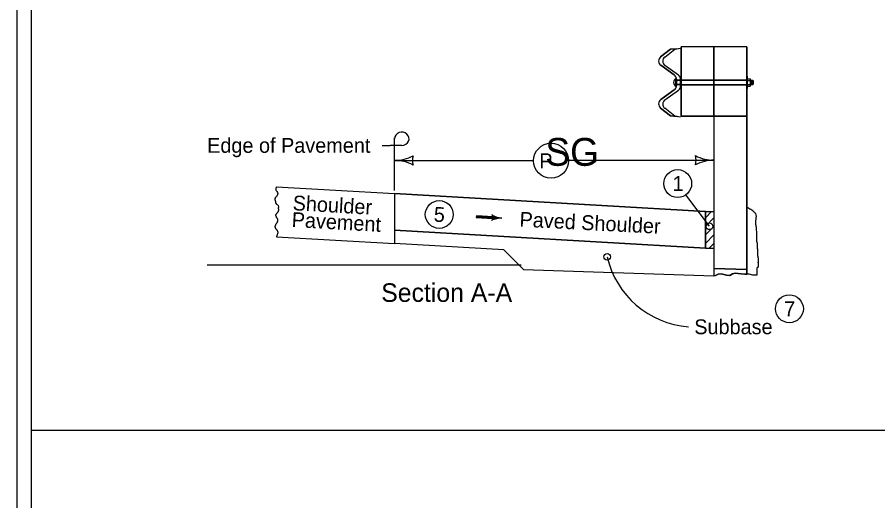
# Model space of a CAD drawing. Extents: x 9538 to 81668, y 7600 to 11751.
# Drawn here: x 24533 to 25461, y 8764 to 9286 of the extents above; entities that cross this region are included whole.
import ezdxf

# ---------------------------------------------------------------- set-up
doc = ezdxf.new("R2010")
doc.units = 0
for name, color, linetype in [('Default', 7, 'Continuous'), ('DsnShtMinorGrid13', 7, 'Continuous'), ('DsnShtMinorGrid14', 7, 'Continuous'), ('dsnStdCells', 7, 'Continuous'), ('dsnStdDimension', 7, 'Continuous'), ('dsnStdNameDate', 7, 'Continuous'), ('dsnStdNote', 7, 'Continuous'), ('dsnStdShading', 7, 'Continuous'), ('dsnStdTable', 7, 'Continuous')]:
    doc.layers.add(name, color=color, linetype=linetype)

msp = doc.modelspace()

# ---------------------------------------------------------------- linework, layer by layer
at = {"layer": 'Default'}
msp.add_lwpolyline([(24532.55, 9944.02), (27667.56, 9944.02), (27667.56, 7924.02), (24532.55, 7924.02)], close=True, dxfattribs=at)
at = {"layer": 'DsnShtMinorGrid13'}
for centre, radius in [((25244.81, 9106.23), 15), ((24987.61, 9072.86), 15), ((25278.94, 9060.11), 3.58), ((25365.26, 8971.18), 15)]:
    msp.add_circle(centre, radius, dxfattribs=at)
at = {"layer": 'DsnShtMinorGrid14'}
msp.add_circle((25168.62, 9027.15), 3.54, dxfattribs=at)
at = {"layer": 'dsnStdCells'}
for p, q in [((25226.58, 9233.67), (25241.09, 9223.26)), ((25241.09, 9207.18), (25226.58, 9196.77))]:
    msp.add_line(p, q, dxfattribs=at)
for points in [[(25283.87, 9217.88), (25283.87, 9253.55), (25248.33, 9253.55), (25248.33, 9217.88), (25248.33, 9217.88), (25283.87, 9217.88)], [(25319.42, 9217.88), (25319.42, 9221.88), (25319.42, 9253.55), (25283.87, 9253.55), (25283.87, 9217.88), (25319.42, 9217.88)], [(25230.83, 9242.57), (25230.82, 9242.56), (25241.6, 9250.97), (25243.48, 9251.3), (25237.15, 9251.19), (25226.39, 9242.79)], [(25245.54, 9223.04), (25245.57, 9223.02), (25231, 9233.48), (25231.03, 9233.45)], [(25243.49, 9218.63), (25243.49, 9217.55), (25247.93, 9217.55), (25247.93, 9218.41), (25247.93, 9218.41)], [(25248.33, 9217.55), (25248.33, 9212.88), (25248.33, 9212.88), (25283.87, 9212.88), (25283.87, 9217.55), (25248.33, 9217.55), (25248.33, 9217.55)], [(25319.42, 9212.88), (25319.42, 9217.55), (25283.87, 9217.55), (25283.87, 9212.88), (25319.42, 9212.88)], [(25231.03, 9196.55), (25231, 9196.53), (25245.57, 9206.99), (25245.54, 9206.96)], [(25247.93, 9211.6), (25247.93, 9211.6), (25247.93, 9212.88), (25243.49, 9212.88), (25243.49, 9211.82), (25243.49, 9212.88), (25243.49, 9212.88), (25243.49, 9211.82)], [(25248.33, 9212.55), (25248.33, 9178.9), (25283.87, 9178.9), (25283.87, 9212.55), (25248.33, 9212.55)], [(25319.42, 9178.9), (25319.42, 9208.55), (25319.42, 9212.55), (25283.87, 9212.55), (25283.87, 9178.9), (25319.42, 9178.9)], [(25226.39, 9187.65), (25237.15, 9179.25), (25244.26, 9178.56), (25241.6, 9179.03), (25230.82, 9187.44), (25230.83, 9187.43)], [(25319.42, 9013.57), (25319.42, 9178.9), (25283.87, 9178.9), (25283.87, 9075.94), (25283.87, 9069.25), (25283.87, 9069.25), (25283.87, 9069.25), (25283.87, 9060.02), (25283.87, 9060.02), (25283.87, 9060.02), (25283.87, 9050.88), (25283.87, 9050.88), (25283.87, 9050.88), (25283.87, 9043.95), (25283.87, 9014.73), (25319.42, 9013.57)], [(25319.42, 9013.57), (25283.87, 9014.73), (25283.87, 9006.67), (25285.69, 9006.92), (25288.44, 9008.51), (25291.73, 9009.04), (25297.35, 9007.45), (25301.05, 9007.24), (25303.7, 9009.04), (25306.78, 9009.68), (25313.03, 9008.94), (25317.27, 9008.51), (25319.42, 9008.51), (25319.42, 9013.57)]]:
    msp.add_lwpolyline(points, dxfattribs=at)
msp.add_lwpolyline([(25247.93, 9217.55), (25243.49, 9217.55), (25243.49, 9214.09), (25243.49, 9215.22), (25243.49, 9212.88), (25247.93, 9212.88)], close=True, dxfattribs=at)
for centre, start, end in [((25229.86, 9238.31), 127.75002, 234.69086), ((25234.31, 9238.09), 127.75002, 234.69086), ((25237.81, 9218.63), 0, 54.69099), ((25242.26, 9218.41), 0, 54.69099), ((25237.81, 9211.82), 305.30901, 0), ((25242.26, 9211.6), 305.30901, 0), ((25229.86, 9192.14), 125.30914, 232.24998), ((25234.31, 9191.92), 125.30914, 232.24998)]:
    msp.add_arc(centre, 5.68, start, end, dxfattribs=at)
at = {"layer": 'dsnStdDimension'}
for p, q in [((24939.48, 9131.19), (25089.32, 9131.19)), ((25127.17, 9131.34), (25283.87, 9131.34))]:
    msp.add_line(p, q, dxfattribs=at)
msp.add_circle((25108.24, 9130.78), 18.93, dxfattribs=at)
for centre, radius, start, end in [((24939.48, 9173.69), 42.5, 270, 298.07249), ((24975.12, 9131.19), 16.42, 162.26665, 197.73335), ((25248.24, 9131.34), 16.42, 342.26665, 17.73335), ((25283.87, 9173.84), 42.5, 241.92751, 270), ((24939.48, 9088.69), 42.5, 61.92751, 90), ((25283.87, 9088.84), 42.5, 90, 118.07249), ((25263.85, 9049.27), 97.76, 193.07698, 265.55799)]:
    msp.add_arc(centre, radius, start, end, dxfattribs=at)
at = {"layer": 'dsnStdNameDate'}
for p, q in [((25278.94, 9060.11), (25253.55, 9094.04)), ((26703.13, 8840.02), (24547.55, 8840.02))]:
    msp.add_line(p, q, dxfattribs=at)
at = {"layer": 'dsnStdNote'}
for p, q in [((24939.48, 9134.51), (24939.48, 9155.37)), ((24926.11, 9147.35), (24934.8, 9147.35)), ((24947.3, 9147.35), (24934.8, 9147.35)), ((24939.48, 9098.57), (24939.48, 9134.51)), ((25045.87, 9069.47), (25027.66, 9070.52)), ((25045.77, 9068.53), (25045.77, 9068.53)), ((25045.88, 9070.47), (25045.88, 9070.47))]:
    msp.add_line(p, q, dxfattribs=at)
for points in [[(25045.9, 9070.41), (25027.73, 9071.46), (25027.6, 9069.58), (25045.77, 9068.53), (25045.82, 9070.14), (25027.95, 9071.23), (25027.89, 9069.74), (25045.38, 9068.79), (25045.51, 9069.91), (25028.18, 9070.97), (25028.16, 9069.97), (25045.17, 9068.99), (25045.26, 9069.69), (25028.37, 9070.75), (25028.36, 9070.19), (25044.96, 9069.25)], [(25045.49, 9071.66), (25046.19, 9070.5), (25046.16, 9068.85), (25045.4, 9067.45), (25048.16, 9068.32), (25051.35, 9068.97), (25052.25, 9069.1), (25050.01, 9069.65), (25046.78, 9070.88), (25045.84, 9071.41), (25045.96, 9067.9), (25050.91, 9069.12), (25046.27, 9070.7), (25046.28, 9068.28), (25049.68, 9069.21), (25046.68, 9070.07), (25046.45, 9068.69), (25048.61, 9069.19), (25047.02, 9069.7), (25046.88, 9069.04), (25047.67, 9069.2)]]:
    msp.add_lwpolyline(points, dxfattribs=at)
for centre, major_axis, start_param, end_param in [((24947.3, 9154.49), (-7.81, 0), 1.570796, 6.283185), ((25042.1, 9069.68), (3.88, 0), 5.202895, 7.237436), ((25054.37, 9048.69), (22.17, 0), 1.537172, 2.061295), ((25057.16, 9089.11), (-22.17, 0), 0.954258, 1.478381)]:
    msp.add_ellipse(centre, major_axis=major_axis, ratio=0.913811, start_param=start_param, end_param=end_param, dxfattribs=at)
at = {"layer": 'dsnStdShading'}
msp.add_line((24547.55, 9929.02), (24547.55, 8319.02), dxfattribs=at)
at = {"layer": 'dsnStdTable'}
for p, q in [((25241.6, 9250.97), (25247.93, 9252.09)), ((25319.42, 9253.55), (25248.33, 9253.55)), ((25248.33, 9178.9), (25248.33, 9253.55)), ((25283.87, 9178.9), (25283.87, 9253.55)), ((25319.42, 9253.55), (25319.42, 9008.51)), ((25226.39, 9242.79), (25237.15, 9251.19)), ((25230.82, 9242.56), (25241.6, 9250.97)), ((25237.15, 9251.19), (25243.48, 9251.3)), ((25241.09, 9223.26), (25226.58, 9233.67)), ((25245.57, 9223.02), (25231, 9233.48)), ((25242.71, 9211.15), (25242.71, 9219.24)), ((25242.71, 9217.55), (25248.14, 9217.55)), ((25243.49, 9211.82), (25243.49, 9218.63)), ((25243.49, 9211.82), (25243.49, 9215.22)), ((25243.49, 9215.22), (25243.49, 9211.82)), ((25243.66, 9217.55), (25248.33, 9217.55)), ((25247.93, 9215), (25247.93, 9218.41)), ((25247.93, 9211.6), (25247.93, 9215)), ((25247.93, 9215), (25247.93, 9211.6)), ((25248.33, 9217.88), (25319.42, 9217.88)), ((25248.33, 9217.55), (25319.42, 9217.55)), ((25319.42, 9221.85), (25320.1, 9221.85)), ((25320.1, 9208.52), (25320.1, 9221.85)), ((25320.1, 9219.23), (25323.07, 9219.23)), ((25320.1, 9217.2), (25323.07, 9217.2)), ((25323.43, 9212.15), (25323.43, 9218.21)), ((25323.43, 9217.52), (25325.81, 9217.52)), ((25324.32, 9217.52), (25324.32, 9212.85)), ((25325.07, 9217.52), (25325.07, 9212.85)), ((25325.81, 9217.52), (25326.25, 9216.98)), ((25325.81, 9217.52), (25325.81, 9212.85)), ((25326.25, 9216.98), (25326.25, 9213.39)), ((25226.58, 9196.77), (25241.09, 9207.18)), ((25231, 9196.53), (25245.57, 9206.99)), ((25242.71, 9212.88), (25248.33, 9212.88)), ((25248.32, 9212.55), (25319.42, 9212.55)), ((25248.33, 9212.88), (25319.42, 9212.88)), ((25319.42, 9208.52), (25320.1, 9208.52)), ((25320.1, 9213.16), (25323.07, 9213.16)), ((25320.1, 9211.14), (25323.07, 9211.14)), ((25323.43, 9212.85), (25325.81, 9212.85)), ((25326.25, 9213.39), (25325.81, 9212.85)), ((25237.15, 9179.25), (25226.39, 9187.65)), ((25241.6, 9179.03), (25230.82, 9187.44)), ((25244.26, 9178.56), (25237.15, 9179.25)), ((25247.93, 9177.92), (25241.6, 9179.03)), ((25283.87, 9178.9), (25248.33, 9178.9)), ((25283.87, 9178.9), (25283.87, 9006.67)), ((24812.02, 9102.84), (24939.48, 9095.43)), ((24939.48, 9095.43), (24939.48, 9041.42)), ((24939.48, 9095.43), (25274.62, 9075.94)), ((25274.62, 9075.94), (24939.48, 9095.43)), ((24939.48, 9095.43), (24939.48, 9055.83)), ((25274.62, 9069.2), (25281.37, 9075.94)), ((25274.62, 9069.2), (25281.37, 9075.94)), ((25274.62, 9069.2), (25281.37, 9075.94)), ((25274.62, 9069.2), (25281.37, 9075.94)), ((25274.62, 9075.94), (25283.86, 9075.94)), ((25274.62, 9075.94), (25274.62, 9036.51)), ((25274.62, 9036.51), (25274.62, 9075.94)), ((25274.62, 9060.01), (25283.86, 9069.25)), ((25274.62, 9060.01), (25283.86, 9069.25)), ((25274.62, 9060.01), (25283.86, 9069.25)), ((25274.62, 9060.01), (25283.86, 9069.25)), ((25329.47, 9069.17), (25329.47, 9069.17)), ((25274.62, 9050.78), (25283.86, 9060.02)), ((25274.62, 9050.78), (25283.86, 9060.02)), ((25274.62, 9050.78), (25283.86, 9060.02)), ((25274.62, 9050.78), (25283.86, 9060.02)), ((24812.05, 9048.83), (24939.48, 9041.42)), ((25274.62, 9036.51), (24939.48, 9055.83)), ((24939.48, 9055.83), (25274.62, 9036.51)), ((25274.62, 9041.56), (25283.86, 9050.79)), ((25057.32, 9034.62), (24939.48, 9041.42)), ((25278.72, 9036.51), (25283.86, 9041.65)), ((25057.32, 9034.62), (25078.66, 9013.41)), ((25274.62, 9036.51), (25283.86, 9036.51)), ((24737.43, 9018.58), (25075.93, 9018.58)), ((25078.66, 9013.41), (25283.87, 9006.67))]:
    msp.add_line(p, q, dxfattribs=at)
for points in [[(25323.13, 9217.21), (25323.21, 9217.25), (25323.28, 9217.35), (25323.36, 9217.57), (25323.42, 9217.86), (25323.42, 9215.91), (25323.36, 9216.43), (25323.31, 9216.8), (25323.19, 9217.12), (25323.14, 9217.21), (25323.19, 9217.21), (25323.3, 9217.36), (25323.38, 9217.59), (25323.4, 9217.74), (25323.41, 9216.2), (25323.33, 9216.7), (25323.28, 9216.96), (25323.17, 9217.18), (25323.2, 9217.2), (25323.34, 9217.41), (25323.38, 9217.57), (25323.39, 9216.46), (25323.2, 9217.17), (25323.36, 9217.45), (25323.37, 9216.6), (25323.22, 9217.16), (25323.34, 9217.38), (25323.35, 9216.74), (25323.24, 9217.14), (25323.33, 9217.32), (25323.33, 9216.9), (25323.26, 9217.13), (25323.31, 9217.25), (25323.31, 9217.04), (25323.28, 9217.11), (25323.29, 9217.16)], [(25323.42, 9212.48), (25323.38, 9212.74), (25323.33, 9212.92), (25323.24, 9213.07), (25323.12, 9213.17), (25323.2, 9213.26), (25323.28, 9213.49), (25323.34, 9213.8), (25323.42, 9214.55), (25323.42, 9212.47), (25323.4, 9212.62), (25323.36, 9212.83), (25323.28, 9213.04), (25323.17, 9213.15), (25323.2, 9213.24), (25323.26, 9213.39), (25323.36, 9213.89), (25323.41, 9214.27), (25323.4, 9212.67), (25323.38, 9212.79), (25323.33, 9212.95), (25323.2, 9213.15), (25323.25, 9213.32), (25323.33, 9213.66), (25323.39, 9213.98), (25323.38, 9212.82), (25323.34, 9212.95), (25323.23, 9213.14), (25323.27, 9213.36), (25323.33, 9213.62), (25323.36, 9213.79), (25323.36, 9212.93), (25323.3, 9213.03), (25323.25, 9213.15), (25323.34, 9213.61), (25323.34, 9213.01), (25323.27, 9213.14), (25323.32, 9213.44), (25323.32, 9213.08), (25323.29, 9213.15), (25323.3, 9213.25), (25323.3, 9213.18)], [(25329.94, 9045.33), (25329.88, 9045.06), (25329.88, 9044.86), (25329.88, 9044.67), (25329.88, 9044.47), (25329.88, 9044.28), (25329.88, 9044.08), (25329.88, 9043.79), (25329.88, 9043.59), (25329.98, 9043.3), (25330.08, 9043.01), (25330.27, 9042.81), (25330.27, 9042.62), (25330.37, 9042.42), (25330.37, 9042.23), (25330.37, 9042.03), (25330.47, 9041.93), (25330.47, 9041.74), (25330.47, 9041.54), (25330.47, 9041.35), (25330.47, 9041.15), (25330.47, 9040.96), (25330.47, 9040.66), (25330.47, 9040.37), (25330.47, 9040.17), (25330.47, 9039.88), (25330.47, 9039.69), (25330.47, 9039.49), (25330.57, 9039.39), (25330.57, 9039.2), (25330.57, 9039), (25330.57, 9038.81), (25330.57, 9038.61), (25330.57, 9038.42), (25330.57, 9038.22), (25330.57, 9038.02), (25330.57, 9037.83), (25330.57, 9037.63), (25330.57, 9037.44), (25330.57, 9037.24), (25330.57, 9037.05), (25330.57, 9036.85), (25330.57, 9036.66), (25330.57, 9036.46), (25330.57, 9036.27), (25330.57, 9036.07), (25330.57, 9035.88), (25330.66, 9035.78), (25330.66, 9035.58), (25330.66, 9035.39), (25330.76, 9035.29), (25330.76, 9035.09), (25330.76, 9034.9), (25330.86, 9034.8), (25330.86, 9034.61), (25330.86, 9034.41), (25330.86, 9034.21), (25330.86, 9033.92), (25330.96, 9033.63), (25330.96, 9033.43), (25330.96, 9033.24), (25330.96, 9033.04), (25330.96, 9032.85), (25330.96, 9032.65), (25330.96, 9032.46), (25330.96, 9032.26), (25330.96, 9032.06), (25330.96, 9031.87), (25330.96, 9031.67), (25330.96, 9031.48), (25330.96, 9031.28), (25330.96, 9031.09), (25330.96, 9030.89), (25330.96, 9030.7), (25330.96, 9030.5), (25330.96, 9030.31), (25330.96, 9030.11), (25330.96, 9029.92), (25330.96, 9029.72), (25330.96, 9029.52), (25330.96, 9029.33), (25330.96, 9029.13), (25330.96, 9028.94), (25330.96, 9028.74), (25330.96, 9028.55), (25330.96, 9028.35), (25330.96, 9028.16), (25330.96, 9027.96), (25331.06, 9027.86), (25331.06, 9027.57), (25331.06, 9027.37), (25331.15, 9027.18), (25331.25, 9026.89), (25331.25, 9026.69), (25331.35, 9026.59), (25331.35, 9026.4), (25331.45, 9026.3), (25331.54, 9026.2), (25331.54, 9026.01), (25331.54, 9025.81), (25331.54, 9025.62), (25331.64, 9025.52), (25331.64, 9025.32), (25331.64, 9025.13), (25331.64, 9024.93), (25331.64, 9024.74), (25331.64, 9024.54), (25331.64, 9024.35), (25331.64, 9024.15), (25331.64, 9023.96), (25331.64, 9023.76), (25331.64, 9023.56), (25331.64, 9023.37), (25331.64, 9023.17), (25331.64, 9022.98), (25331.64, 9022.78), (25331.64, 9022.59), (25331.64, 9022.39), (25331.64, 9022.2), (25331.64, 9022), (25331.64, 9021.81), (25331.64, 9021.61), (25331.64, 9021.42), (25331.64, 9021.22), (25331.64, 9021.02), (25331.64, 9020.83), (25331.64, 9020.63), (25331.64, 9020.63), (25331.64, 9020.93), (25331.64, 9021.12), (25331.64, 9021.32), (25331.64, 9021.12), (25331.64, 9020.93), (25331.64, 9020.73), (25331.64, 9020.54), (25331.64, 9020.34), (25331.64, 9020.14), (25331.64, 9019.95), (25331.64, 9019.75), (25331.64, 9019.56), (25331.64, 9019.36), (25331.64, 9019.17), (25331.64, 9018.97), (25331.64, 9018.78), (25331.64, 9018.58), (25331.64, 9018.39), (25331.54, 9018.29), (25331.54, 9018.09), (25331.54, 9017.9), (25331.54, 9017.7), (25331.54, 9017.51), (25331.54, 9017.31), (25331.54, 9017.12), (25331.54, 9016.92), (25331.54, 9016.73), (25331.54, 9016.53), (25331.54, 9016.33), (25331.45, 9016.24), (25331.35, 9016.04), (25331.25, 9015.94), (25331.15, 9015.85), (25331.06, 9015.75), (25330.86, 9015.65), (25330.66, 9015.65), (25330.57, 9015.55), (25330.47, 9015.46), (25330.37, 9015.36), (25330.18, 9015.26), (25330.08, 9015.16), (25330.08, 9014.97), (25329.98, 9014.87), (25329.98, 9014.67), (25329.98, 9014.48), (25329.98, 9014.28), (25329.98, 9007.46)], [(25330.11, 9007.47), (25325.96, 9007.35), (25321.83, 9008.51), (25317.27, 9008.51), (25313.03, 9008.94), (25306.78, 9009.68), (25303.7, 9009.04), (25301.05, 9007.24), (25297.35, 9007.45), (25291.73, 9009.04), (25288.44, 9008.51), (25285.69, 9006.92), (25283.87, 9006.67)]]:
    msp.add_lwpolyline(points, dxfattribs=at)
msp.add_circle((24987.61, 9072.86), 15, dxfattribs=at)
for centre, radius, start, end in [((25229.86, 9238.31), 5.68, 127.75002, 234.69086), ((25234.31, 9238.09), 5.68, 127.75002, 234.69086), ((25244.79, 9215.2), 4.54, 117.20289, 242.8461), ((25237.81, 9218.63), 5.68, 360, 54.69099), ((25242.26, 9218.41), 5.68, 360, 54.69099), ((25237.81, 9211.82), 5.68, 305.30901, 0), ((25242.26, 9211.6), 5.68, 305.30901, 0), ((25229.86, 9192.14), 5.68, 125.30914, 232.24998), ((25234.31, 9191.92), 5.68, 125.30914, 232.24998)]:
    msp.add_arc(centre, radius, start, end, dxfattribs=at)
for centre in [(25323.07, 9218.21), (25323.07, 9212.15)]:
    msp.add_ellipse(centre, major_axis=(0, -1.01), ratio=0.362258, start_param=6.283156, end_param=9.424748, dxfattribs=at)
for points in [[(24812.02, 9102.84), (24811.52, 9099.24), (24812.56, 9097.73), (24813.42, 9095.44), (24812.82, 9093.38), (24810.91, 9091), (24810.39, 9089.1), (24810.91, 9086.8), (24811.78, 9084.43), (24812.82, 9083.72), (24814.2, 9081.18), (24814.19, 9080.34)], [(24812.23, 9063.23), (24812.44, 9063.48), (24812.64, 9063.74), (24812.99, 9064.3), (24813.27, 9064.89), (24813.39, 9065.19), (24813.49, 9065.51), (24813.62, 9066.13), (24813.67, 9066.75), (24813.62, 9067.34), (24813.57, 9067.61), (24813.53, 9067.75), (24813.48, 9067.88), (24813.27, 9068.26), (24812.99, 9068.62), (24812.69, 9068.99), (24812.44, 9069.38), (24812.3, 9069.67), (24812.16, 9069.95), (24811.9, 9070.52), (24811.7, 9071.09), (24811.63, 9071.38), (24811.57, 9071.68), (24811.56, 9071.81), (24811.56, 9071.94), (24811.71, 9072.71), (24811.92, 9073.23), (24812.18, 9073.74), (24812.63, 9074.38), (24813.14, 9074.92), (24813.66, 9075.47), (24813.89, 9075.78), (24814.09, 9076.12), (24814.3, 9076.59), (24814.45, 9077.06), (24814.55, 9077.54), (24814.59, 9077.78), (24814.6, 9077.9), (24814.61, 9078.02), (24814.56, 9078.53), (24814.41, 9079.04), (24814.36, 9079.17), (24814.3, 9079.29), (24814.26, 9079.42), (24814.23, 9079.55), (24814.19, 9080.34)], [(25329.94, 9045.33), (25330.26, 9048.24), (25330.04, 9053.1), (25329.6, 9058.85), (25328.94, 9063.27), (25329.16, 9066.59), (25329.6, 9070.79), (25328.94, 9073.89), (25326.72, 9075.88), (25324.73, 9077.65), (25322.52, 9078.75), (25320.31, 9080.08), (25319.43, 9080.74)], [(24812.23, 9063.23), (24812.02, 9062.99), (24811.77, 9062.76), (24811.53, 9062.52), (24811.35, 9062.25), (24811.21, 9061.97), (24811.07, 9061.68), (24810.81, 9061.11), (24810.7, 9060.83), (24810.61, 9060.54), (24810.53, 9060.25), (24810.51, 9060.1), (24810.48, 9059.95), (24810.49, 9059.44), (24810.62, 9058.92), (24810.83, 9058.4), (24811.09, 9057.89), (24811.54, 9057.26), (24812.05, 9056.71), (24812.57, 9056.16), (24812.8, 9055.86), (24813, 9055.52), (24813.4, 9054.57), (24813.51, 9054.1), (24813.52, 9053.62), (24813.48, 9053.33), (24813.44, 9053.04), (24813.38, 9052.75), (24813.31, 9052.47), (24813, 9051.32), (24812.82, 9050.71), (24812.62, 9050.11), (24812.4, 9049.52), (24812.27, 9049.23), (24812.13, 9048.94), (24812.05, 9048.83)]]:
    msp.add_spline(points, degree=3, dxfattribs=at)

# ---------------------------------------------------------------- texts
at = {"layer": 'DsnShtMinorGrid13'}
for s, p in [('1', (25239.19, 9098.23)), ('7', (25359.55, 8963.18))]:
    msp.add_text(s, height=16, dxfattribs=at).set_placement(p)
msp.add_text('5', height=16, rotation=356.69973, dxfattribs=at).set_placement((24981.39, 9065.2))
at = {"layer": 'dsnStdDimension'}
for s, height, p in [('SG', 30, (25101.96, 9125.34)), ('P', 16, (25095.53, 9122.78))]:
    msp.add_text(s, height=height, dxfattribs=at).set_placement(p)
at = {"layer": 'dsnStdNote'}
for s, height, p in [('Edge of Pavement', 16, (24737.35, 9139.35)), ('Section A-A', 20, (24925.06, 8978.66)), ('Subbase', 16, (25262.63, 8943.8))]:
    msp.add_text(s, height=height, dxfattribs=at).set_placement(p)
for s, rotation, p in [('Shoulder', 356.73462, (24829.24, 9077.5)), ('Paved Shoulder ', 357.0678, (25073.88, 9059.83)), ('Pavement', 356.73462, (24828.22, 9059.53))]:
    msp.add_text(s, height=16, rotation=rotation, dxfattribs=at).set_placement(p)

doc.saveas('drawing.dxf')
